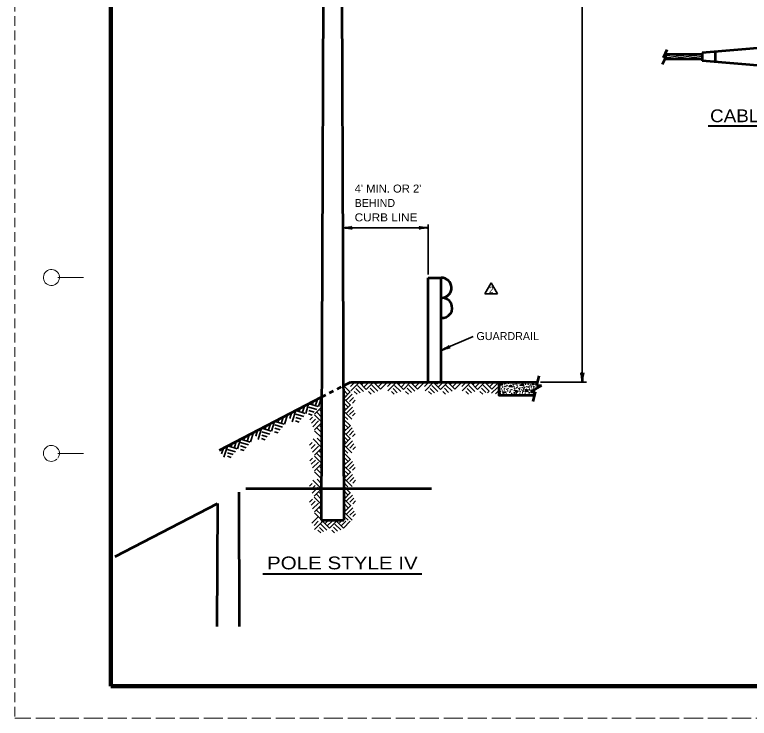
# Model space of a CAD drawing. Extents: x -1 to 679, y 0 to 440.
# Drawn here: x -1.2 to 228.3, y 0.2 to 220.2 of the extents above; entities that cross this region are included whole.
import ezdxf

# ---------------------------------------------------------------- set-up
doc = ezdxf.new("R2010")
doc.units = 0
for name, pattern in [('LONG_DASHED', [7.5, 6, -1.5]), ('MEDIUM_DASHED', [4.5, 3, -1.5]), ('SHORT_DASHED', [2.7, 1.5, -1.2])]:
    doc.linetypes.add(name, pattern=pattern)
doc.layers.add('1', color=7, linetype='Continuous', lineweight=53)
doc.layers.add('61', color=7, linetype='Continuous', lineweight=35)

msp = doc.modelspace()

# ---------------------------------------------------------------- linework, layer by layer
at = {"layer": '1', "linetype": 'MEDIUM_DASHED', "lineweight": 13}
msp.add_line((-1.129, 440.242), (-1.189, 0.202), dxfattribs=at)
at = {"layer": '1', "lineweight": 35}
for p, q in [((176.14, 105.337), (176.14, 367.754)), ((128.008, 138.952), (128.008, 154.583)), ((128.008, 153.583), (101.302, 153.583)), ((147.666, 136.36), (145.666, 132.896)), ((147.666, 136.36), (149.666, 132.896)), ((149.666, 132.896), (145.666, 132.896)), ((132.1, 115.287), (142.106, 119.577)), ((101.506, 104.275), (103.653, 102.142)), ((105.039, 105.296), (103.684, 103.941)), ((106.497, 105.296), (103.807, 102.606)), ((105.429, 103.325), (106.743, 102.011)), ((105.901, 104.31), (107.811, 102.422)), ((106.394, 105.296), (108.653, 103.038)), ((107.954, 105.296), (107.38, 104.701)), ((109.433, 105.296), (108.016, 103.879)), ((110.89, 105.296), (108.653, 103.038)), ((109.884, 103.387), (111.198, 102.073)), ((110.357, 104.372), (112.245, 102.483)), ((110.89, 105.296), (113.087, 103.099)), ((112.348, 105.296), (111.814, 104.762)), ((113.826, 105.296), (112.471, 103.941)), ((115.284, 105.296), (113.087, 103.099)), ((116.639, 105.296), (115.284, 103.941)), ((118.097, 105.296), (115.407, 102.606)), ((117.029, 103.325), (118.343, 102.011)), ((117.501, 104.31), (119.411, 102.422)), ((117.994, 105.296), (120.253, 103.038)), ((119.554, 105.296), (118.98, 104.701)), ((121.033, 105.296), (119.616, 103.879)), ((122.49, 105.296), (120.253, 103.038)), ((121.484, 103.387), (122.798, 102.073)), ((121.957, 104.372), (123.846, 102.483)), ((122.49, 105.296), (124.687, 103.099)), ((123.948, 105.296), (123.414, 104.762)), ((125.426, 105.296), (124.071, 103.941)), ((126.884, 105.296), (124.687, 103.099)), ((128.239, 105.296), (126.884, 103.941)), ((129.697, 105.296), (127.007, 102.606)), ((128.629, 103.325), (129.943, 102.011)), ((129.101, 104.31), (131.011, 102.422)), ((129.594, 105.296), (131.853, 103.038)), ((131.154, 105.296), (130.58, 104.701)), ((132.633, 105.296), (131.216, 103.879)), ((134.09, 105.296), (131.853, 103.038)), ((133.084, 103.387), (134.398, 102.073)), ((133.557, 104.372), (135.445, 102.483)), ((134.09, 105.296), (136.287, 103.099)), ((135.548, 105.296), (135.014, 104.762)), ((137.026, 105.296), (135.671, 103.941)), ((138.484, 105.296), (136.287, 103.099)), ((139.839, 105.296), (138.484, 103.941)), ((141.297, 105.296), (138.607, 102.606)), ((140.229, 103.325), (141.543, 102.011)), ((140.701, 104.31), (142.611, 102.422)), ((141.194, 105.296), (143.453, 103.038)), ((142.755, 105.296), (142.18, 104.701)), ((144.233, 105.296), (142.816, 103.879)), ((145.69, 105.296), (143.453, 103.038)), ((144.684, 103.387), (145.998, 102.073)), ((145.157, 104.372), (147.046, 102.483)), ((145.69, 105.296), (147.887, 103.099)), ((147.148, 105.296), (146.614, 104.762)), ((148.626, 105.296), (147.271, 103.941)), ((149.687, 103.682), (147.834, 101.828)), ((150.125, 105.337), (147.887, 103.099)), ((163.125, 105.337), (177.45, 105.337)), ((101.51, 102.923), (102.834, 101.608)), ((101.515, 101.554), (102.036, 101.035)), ((101.519, 100.14), (103.652, 102.287)), ((102.421, 99.668), (104.255, 101.514)), ((104.916, 102.381), (105.799, 101.518)), ((109.351, 102.442), (110.233, 101.559)), ((116.516, 102.381), (117.399, 101.518)), ((120.951, 102.442), (121.834, 101.559)), ((128.116, 102.381), (128.999, 101.518)), ((132.551, 102.442), (133.434, 101.559)), ((139.716, 102.381), (140.599, 101.518)), ((144.151, 102.442), (145.034, 101.559)), ((147.051, 102.486), (146.531, 101.966)), ((149.911, 102.486), (149.085, 101.659)), ((92.042, 99.24), (91.82, 98.539)), ((93.377, 99.934), (92.814, 98.154)), ((94.692, 100.618), (93.78, 97.732)), ((101.519, 100.285), (103.726, 98.113)), ((101.523, 98.934), (102.908, 97.559)), ((103.382, 99.261), (104.658, 100.545)), ((104.304, 98.793), (105.161, 99.656)), ((86.613, 96.419), (85.497, 92.885)), ((86.651, 96.438), (89.618, 95.501)), ((88.008, 97.144), (87.778, 96.371)), ((89.342, 97.837), (88.754, 95.976)), ((90.658, 98.521), (89.738, 95.564)), ((90.688, 96.44), (92.414, 95.895)), ((90.694, 97.525), (93.175, 96.741)), ((90.777, 98.583), (93.663, 97.671)), ((94.682, 97.537), (92.475, 95.344)), ((94.677, 95.998), (94.099, 96.56)), ((101.528, 97.564), (102.11, 97.006)), ((101.533, 96.053), (103.726, 98.26)), ((102.494, 95.62), (104.328, 97.486)), ((103.456, 95.214), (104.731, 96.498)), ((82.729, 94.4), (82.167, 92.62)), ((84.044, 95.084), (83.133, 92.198)), ((85.311, 95.742), (84.748, 93.962)), ((86.626, 94.261), (88.352, 93.716)), ((86.632, 95.347), (89.132, 94.572)), ((90.61, 95.363), (91.77, 94.997)), ((91.891, 94.366), (91.029, 93.509)), ((94.666, 92.86), (92.474, 95.047)), ((94.672, 94.418), (93.296, 95.803)), ((101.532, 96.309), (104.161, 93.698)), ((101.536, 94.941), (102.861, 93.626)), ((104.377, 94.765), (105.214, 95.628)), ((78.694, 92.303), (78.107, 90.442)), ((80.011, 92.987), (79.091, 90.029)), ((80.046, 91.991), (82.527, 91.207)), ((80.129, 93.048), (83.015, 92.136)), ((81.394, 93.706), (81.173, 93.005)), ((86.567, 93.194), (87.718, 92.846)), ((92.809, 93.744), (91.525, 92.468)), ((93.768, 93.18), (91.921, 91.346)), ((94.665, 92.566), (92.518, 90.434)), ((101.54, 93.775), (103.688, 91.642)), ((101.545, 92.423), (102.869, 91.108)), ((73.397, 89.549), (72.485, 86.663)), ((74.663, 90.207), (74.101, 88.427)), ((75.966, 90.884), (74.849, 87.351)), ((75.985, 89.812), (78.484, 89.037)), ((76.004, 90.904), (78.971, 89.967)), ((77.36, 91.609), (77.131, 90.836)), ((79.963, 89.829), (81.123, 89.462)), ((80.04, 90.906), (81.766, 90.36)), ((94.65, 87.996), (92.517, 90.143)), ((94.656, 89.553), (93.34, 90.878)), ((94.661, 91.134), (94.142, 91.656)), ((101.549, 91.054), (102.071, 90.535)), ((101.554, 89.64), (103.687, 91.787)), ((101.554, 89.785), (103.761, 87.613)), ((102.456, 89.168), (104.29, 91.014)), ((103.417, 88.761), (104.693, 90.045)), ((69.363, 87.452), (68.443, 84.495)), ((69.482, 87.514), (72.368, 86.602)), ((70.747, 88.171), (70.525, 87.47)), ((72.081, 88.865), (71.519, 87.085)), ((75.92, 87.66), (77.07, 87.311)), ((75.978, 88.727), (77.704, 88.181)), ((94.64, 84.917), (92.029, 87.546)), ((94.645, 86.441), (93.33, 87.766)), ((101.558, 88.434), (102.943, 87.059)), ((101.568, 85.553), (103.76, 87.761)), ((104.339, 88.293), (105.196, 89.156)), ((65.318, 85.349), (64.202, 81.816)), ((65.356, 85.369), (68.323, 84.432)), ((66.713, 86.074), (66.483, 85.301)), ((68.047, 86.768), (67.459, 84.907)), ((69.393, 85.371), (71.119, 84.826)), ((69.399, 86.456), (71.88, 85.672)), ((91.805, 86.439), (90.962, 85.582)), ((92.723, 85.84), (91.439, 84.564)), ((93.681, 85.275), (91.835, 83.421)), ((101.563, 87.064), (102.144, 86.506)), ((101.567, 85.809), (104.195, 83.198)), ((102.529, 85.12), (104.363, 86.986)), ((103.49, 84.714), (104.766, 85.998)), ((104.412, 84.265), (105.249, 85.128)), ((64.016, 84.672), (63.453, 82.892)), ((65.331, 83.192), (67.057, 82.647)), ((65.337, 84.278), (67.836, 83.503)), ((69.315, 84.294), (70.475, 83.928)), ((94.639, 84.703), (92.432, 82.511)), ((94.629, 81.585), (93.254, 82.969)), ((94.634, 83.165), (94.056, 83.726)), ((101.571, 84.441), (102.896, 83.126)), ((101.575, 83.275), (103.722, 81.142)), ((65.272, 82.125), (66.423, 81.776)), ((91.849, 81.533), (90.986, 80.676)), ((92.767, 80.911), (91.483, 79.635)), ((93.725, 80.347), (91.879, 78.513)), ((94.624, 80.026), (92.431, 82.214)), ((101.58, 81.923), (102.904, 80.608)), ((101.584, 80.554), (102.106, 80.035)), ((101.589, 79.14), (103.722, 81.287)), ((102.49, 78.668), (104.324, 80.514)), ((94.623, 79.733), (92.476, 77.6)), ((94.613, 76.72), (93.297, 78.044)), ((94.618, 78.301), (94.1, 78.823)), ((101.588, 79.285), (103.796, 77.113)), ((103.452, 78.261), (104.727, 79.545)), ((104.373, 77.793), (105.23, 78.656)), ((94.608, 75.163), (92.475, 77.31)), ((101.593, 77.934), (102.977, 76.559)), ((101.597, 76.564), (102.179, 76.006)), ((101.602, 75.053), (103.795, 77.261)), ((102.564, 74.62), (104.398, 76.486)), ((91.763, 73.606), (90.92, 72.749)), ((94.598, 72.084), (91.986, 74.712)), ((94.603, 73.608), (93.287, 74.933)), ((101.602, 75.309), (104.23, 72.698)), ((101.606, 73.941), (102.93, 72.626)), ((103.525, 74.214), (104.801, 75.498)), ((104.447, 73.765), (105.284, 74.628)), ((92.681, 73.007), (91.396, 71.731)), ((93.639, 72.442), (91.793, 70.588)), ((94.597, 71.87), (92.39, 69.678)), ((101.61, 72.775), (103.757, 70.642)), ((101.614, 71.424), (102.939, 70.108)), ((94.581, 67.193), (92.389, 69.38)), ((94.587, 68.751), (93.211, 70.136)), ((94.592, 70.331), (94.014, 70.893)), ((101.619, 70.054), (102.141, 69.535)), ((101.624, 68.64), (103.757, 70.787)), ((102.525, 68.168), (104.359, 70.014)), ((103.487, 67.761), (104.762, 69.045)), ((91.806, 68.7), (90.944, 67.842)), ((92.724, 68.078), (91.44, 66.802)), ((93.682, 67.514), (91.836, 65.68)), ((94.581, 66.9), (92.433, 64.767)), ((101.623, 68.785), (103.83, 66.613)), ((101.628, 67.434), (103.012, 66.059)), ((101.637, 64.553), (103.83, 66.761)), ((104.408, 67.293), (105.265, 68.156)), ((94.565, 62.33), (92.432, 64.477)), ((94.57, 63.887), (93.255, 65.211)), ((94.576, 65.468), (94.057, 65.989)), ((101.632, 66.064), (102.214, 65.506)), ((101.636, 64.809), (104.265, 62.198)), ((102.599, 64.12), (104.432, 65.986)), ((103.56, 63.714), (104.836, 64.998)), ((93.529, 63.119), (91.675, 61.265)), ((101.641, 63.441), (102.965, 62.126)), ((104.481, 63.265), (105.319, 64.128)), ((93.672, 61.837), (92.352, 60.517)), ((95.092, 61.837), (92.472, 59.217)), ((94.052, 59.917), (95.332, 58.637)), ((94.512, 60.877), (96.372, 59.037)), ((94.992, 61.837), (97.192, 59.637)), ((96.512, 61.837), (95.952, 61.257)), ((97.952, 61.837), (96.572, 60.457)), ((99.372, 61.837), (97.192, 59.637)), ((98.392, 59.977), (99.672, 58.697)), ((98.852, 60.937), (100.692, 59.097)), ((99.372, 61.837), (101.512, 59.697)), ((100.792, 61.837), (100.272, 61.317)), ((102.232, 61.837), (100.912, 60.517)), ((103.652, 61.837), (101.512, 59.697)), ((93.552, 58.997), (94.412, 58.157)), ((97.872, 59.057), (98.732, 58.197))]:
    msp.add_line(p, q, dxfattribs=at)
at = {"layer": '1'}
for p, q in [((95.605, 364.184), (94.605, 62.184)), ((100.73, 326.266), (101.605, 62.184)), ((201.516, 206.794), (202.676, 209.294)), ((237.256, 210.334), (213.656, 208.254)), ((201.256, 204.794), (202.416, 207.294)), ((201.516, 206.794), (202.416, 207.294)), ((213.656, 207.754), (201.956, 207.754)), ((213.656, 208.254), (213.656, 205.834)), ((217.696, 208.614), (217.696, 205.494)), ((213.656, 206.354), (201.976, 206.354)), ((237.256, 203.774), (213.656, 205.834)), ((128.008, 105.337), (128.008, 137.952)), ((128.008, 137.952), (132.1, 137.952)), ((132.1, 105.337), (132.1, 137.952)), ((162.568, 107.287), (161.876, 104.242)), ((101.466, 104.184), (103.684, 105.337)), ((103.684, 105.337), (162.125, 105.337)), ((163.376, 104.242), (159.933, 102.292)), ((161.876, 104.242), (163.376, 104.242)), ((161.433, 102.292), (159.933, 102.292)), ((161.433, 102.292), (160.741, 99.247)), ((62.79, 84.081), (94.732, 100.684)), ((71.076, 72.033), (129.076, 72.033)), ((68.858, 70.88), (68.997, 28.88)), ((30.182, 50.776), (62.125, 67.38)), ((62.125, 67.38), (61.997, 28.88)), ((94.605, 62.184), (101.605, 62.184))]:
    msp.add_line(p, q, dxfattribs=at)
at = {"layer": '1', "lineweight": 25}
for p, q in [((201.776, 207.334), (205.276, 207.754)), ((201.976, 206.354), (213.656, 207.754)), ((202.216, 206.874), (209.476, 207.754)), ((206.176, 206.354), (213.656, 207.254)), ((210.356, 206.354), (213.656, 206.734))]:
    msp.add_line(p, q, dxfattribs=at)
at = {"layer": '1', "lineweight": 40}
for p, q in [((215.436, 185.414), (272.476, 185.414)), ((76.39, 45.402), (125.991, 45.402))]:
    msp.add_line(p, q, dxfattribs=at)
at = {"layer": '1', "linetype": 'SHORT_DASHED'}
msp.add_line((94.732, 100.684), (101.466, 104.184), dxfattribs=at)
at = {"layer": '1'}
msp.add_lwpolyline([(150.037, 105.337), (150.037, 101.197), (161.184, 101.197)], dxfattribs=at)
at = {"layer": '1', "lineweight": 35}
for points in [[(150.969, 104.865), (150.6, 104.471), (151.179, 104.431), (150.969, 104.839)], [(153.848, 104.365), (153.204, 103.997), (154.164, 103.826), (153.809, 104.379)], [(157.635, 104.734), (156.714, 104.352), (157.74, 104.234), (157.635, 104.694)], [(160.803, 105.023), (160.435, 104.629), (161.014, 104.589), (160.803, 104.997)], [(151.245, 102.327), (152.283, 102.222), (151.613, 101.972), (151.245, 102.34)], [(155.557, 101.919), (155.321, 102.721), (156.096, 102.55), (155.544, 101.959)], [(158.516, 103.116), (159.199, 102.708), (158.345, 102.287), (158.463, 103.129)]]:
    msp.add_lwpolyline(points, dxfattribs=at)
for centre in [(150.482, 103.971), (150.535, 104.944), (151.258, 103.8), (151.863, 104.734), (151.889, 103.3), (151.968, 104.023), (152.31, 104.905), (152.31, 103.984), (152.625, 104.221), (152.967, 103.3), (153.112, 104.997), (153.901, 105.062), (154.519, 104.668), (154.519, 103.931), (154.676, 104.457), (154.9, 103.839), (155.018, 103.274), (155.189, 104.668), (155.557, 103.511), (155.584, 104.826), (155.807, 104.365), (155.86, 104.365), (155.925, 103.787), (156.32, 103.3), (156.359, 104.931), (156.727, 103.524), (157.24, 105.023), (157.372, 103.616), (157.766, 104.102), (157.871, 104.984), (157.898, 103.287), (158.003, 103.603), (158.279, 103.774), (158.397, 104.615), (158.805, 103.892), (159.186, 105.076), (159.226, 104.629), (159.252, 103.747), (159.567, 104.037), (159.673, 103.642), (159.686, 105.128), (159.896, 104.444), (160.251, 104.05), (160.264, 103.734), (160.672, 105.168), (160.882, 103.931), (160.987, 103.458), (161.329, 103.866), (161.579, 104.55), (161.658, 104.931), (162.013, 104.037), (162.697, 104.037), (150.627, 102.353), (150.627, 101.761), (150.837, 103.195), (151.166, 102.682), (151.429, 101.722), (151.837, 102.906), (152.415, 101.643), (152.573, 103.09), (152.849, 102.577), (153.44, 102.169), (153.506, 101.419), (153.717, 102.8), (153.756, 102.314), (154.098, 101.775), (154.124, 102.971), (154.453, 101.577), (154.847, 102.143), (154.887, 102.735), (155.031, 101.722), (155.676, 101.577), (156.596, 102.932), (156.688, 101.788), (156.754, 102.327), (157.109, 102.906), (157.451, 101.564), (157.529, 102.577), (157.543, 102.064), (157.819, 102.511), (157.832, 102.984), (158.148, 101.538), (158.424, 101.656), (159.16, 102.366), (159.199, 101.472), (159.489, 101.972), (159.62, 103.09), (159.712, 101.972), (159.844, 102.8), (160.172, 101.485), (160.422, 103.142), (160.869, 101.932), (160.935, 101.617)]:
    msp.add_circle(centre, 0.0262, dxfattribs=at)
at = {"layer": '1'}
for centre, start in [((132.153, 134.812), 273.05603), ((132.373, 128.536), 262.79463)]:
    msp.add_arc(centre, 3.141, start, 90.95751, dxfattribs=at)
at = {"layer": '1', "lineweight": 40}
for centre, major_axis, ratio, start_param, end_param in [((102.394, 153.86), (-1.786, -0.156), 0.122415, 0.8963533, 3.1415927), ((102.394, 153.86), (-1.786, -0.156), 0.122415, 0.8963533, 3.1415927), ((126.888, 153.795), (1.756, -0.176), 0.07063, 3.1407148, 5.41811), ((102.423, 153.372), (-1.756, 0.176), 0.07063, 3.1407148, 5.41811), ((102.423, 153.372), (-1.756, 0.176), 0.07063, 3.1407148, 5.41811), ((126.917, 153.307), (1.786, 0.156), 0.122415, 0.8963533, 3.1415927), ((132.994, 115.971), (-1.58, -0.847), 0.122415, 0.8963533, 3.1415927), ((133.214, 115.534), (-1.684, -0.531), 0.07063, 3.1407148, 5.41811), ((175.864, 106.428), (0.156, -1.786), 0.122415, 0.8963533, 3.1415927), ((175.864, 106.428), (0.156, -1.786), 0.122415, 0.8963533, 3.1415927), ((176.352, 106.458), (-0.176, -1.756), 0.07063, 3.1407148, 5.41811), ((176.352, 106.458), (-0.176, -1.756), 0.07063, 3.1407148, 5.41811)]:
    msp.add_ellipse(centre, major_axis=major_axis, ratio=ratio, start_param=start_param, end_param=end_param, dxfattribs=at)
at = {"layer": '61', "lineweight": 13}
for p, q in [((12.291, 138.062), (20.291, 138.062)), ((12.311, 83.042), (20.291, 83.042))]:
    msp.add_line(p, q, dxfattribs=at)
at = {"layer": '61', "lineweight": 158}
msp.add_line((667.931, 10.202), (28.871, 10.222), dxfattribs=at)
at = {"layer": '61', "linetype": 'LONG_DASHED', "lineweight": 13}
msp.add_line((678.871, 0.222), (-1.189, 0.202), dxfattribs=at)
at = {"layer": '61', "lineweight": 158}
msp.add_lwpolyline([(667.911, 430.242), (28.871, 430.242), (28.871, 10.222)], dxfattribs=at)
at = {"layer": '61', "lineweight": 13}
for centre, start, end in [((10.289, 138.043), 322.67175, 321.71615), ((10.289, 83.043), 323.13009, 312.31439)]:
    msp.add_arc(centre, 2.5, start, end, dxfattribs=at)

# ---------------------------------------------------------------- texts
at = {"layer": '1'}
for s, height, width, p in [('CABLE STRANVISE', 4, 1.1, (216.081, 186.607)), ("4' MIN. OR 2'", 2.5, 1.05, (105.027, 164.594)), ('CURB LINE', 2.5, 1.1, (105.027, 155.594)), ('2', 2, 0.9, (147.03, 133.177)), ('POLE STYLE IV', 4, 1.2, (77.633, 46.784))]:
    msp.add_text(s, height=height, dxfattribs=dict(at, width=width)).set_placement(p)
for s, p in [('BEHIND', (105.027, 160.094)), ('GUARDRAIL', (143.096, 118.477))]:
    msp.add_text(s, height=2.5, dxfattribs=at).set_placement(p)

doc.saveas('drawing.dxf')
